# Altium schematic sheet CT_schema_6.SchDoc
size 252 x 245 mm
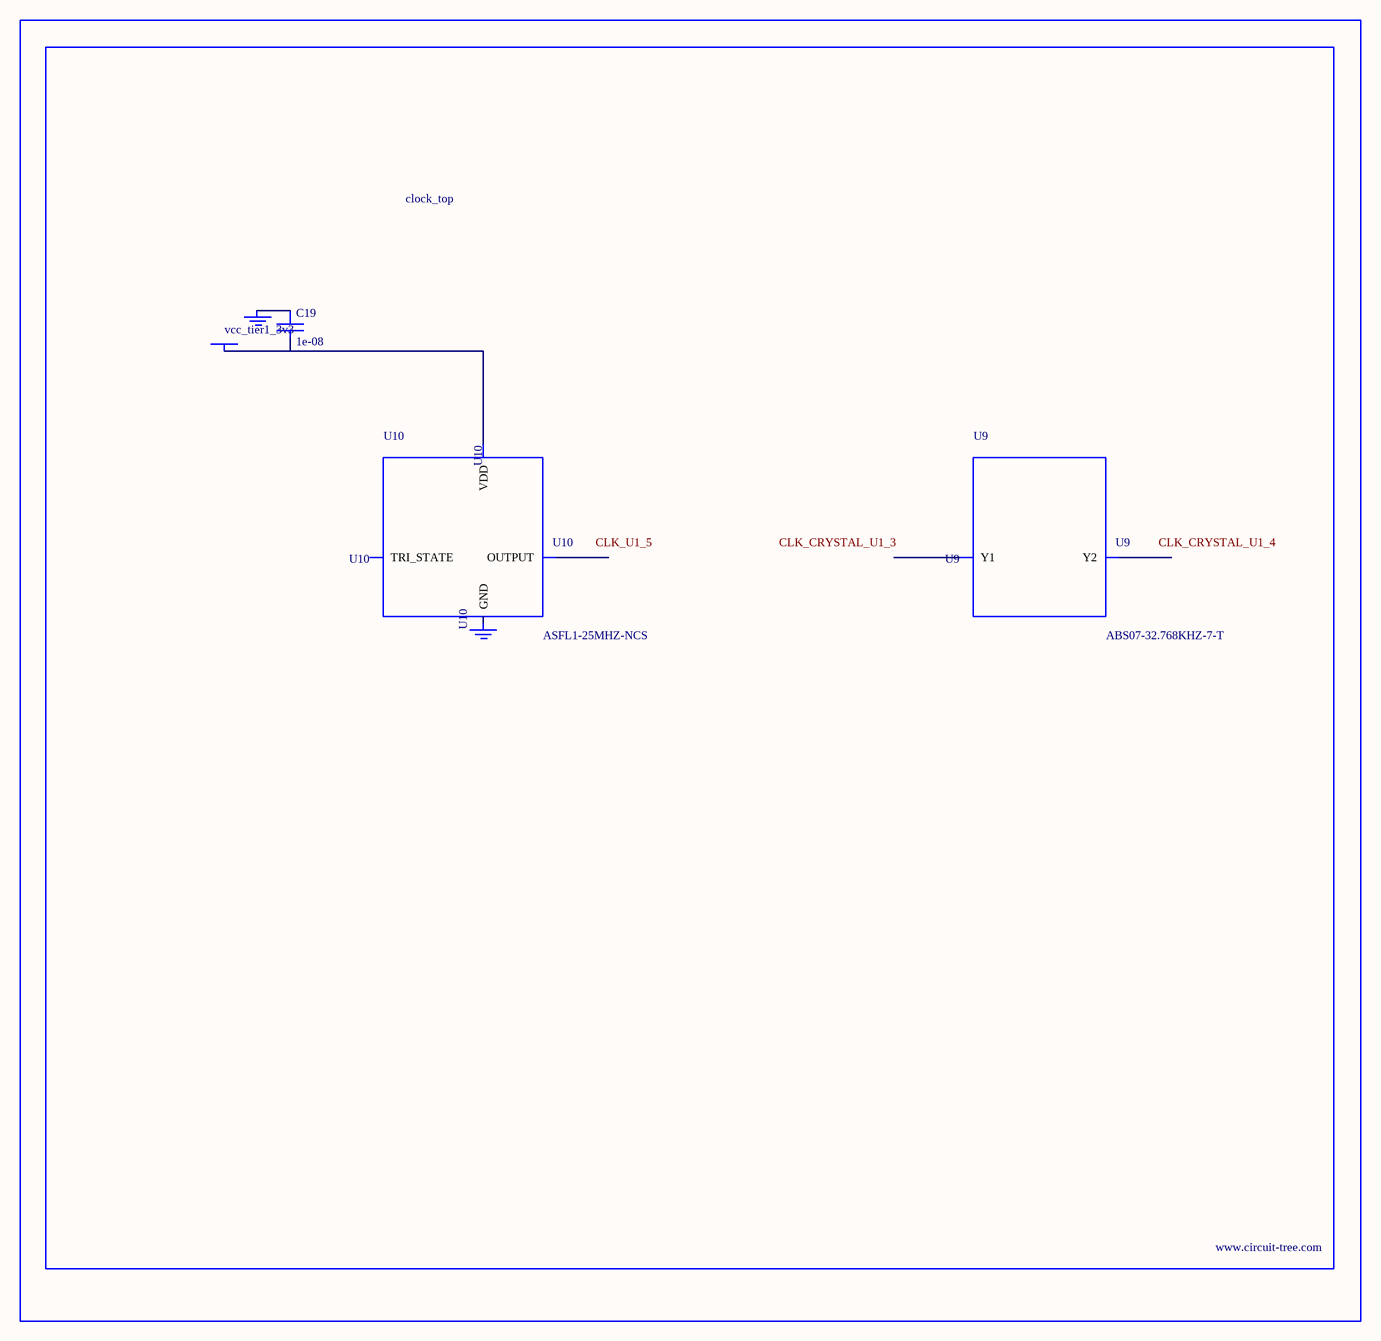
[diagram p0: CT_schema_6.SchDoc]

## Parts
BORDER5  (no value)
C19  1e-08  [C0402]
GND_INSTANCE_5_0  (no value)
GND_INSTANCE_5_1  (no value)
POWER_INSTANCE_5_0  vcc_tier1_3v3
U9  ABS07-32.768KHZ-7-T  [ABS07-32.768KHZ-7-T]
U10  ASFL1-25MHZ-NCS  [ASFL1]

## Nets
NetC19_1: C19.1 GND_INSTANCE_5_0.0(GND)
NetC19_2: C19.2 POWER_INSTANCE_5_0.0(PWR) U10.4(VDD)

Not connected (* = marked no-connect by the designer): GND_INSTANCE_5_1 0(GND); U9 1(Y1) 2(Y2); U10 1(TRI_STATE) 2(GND) 3(OUTPUT)

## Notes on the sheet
- Labels drawn without touching a wire or pin: CLK_CRYSTAL_U1_3, CLK_CRYSTAL_U1_4, CLK_U1_5

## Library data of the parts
BORDER5 = BORDER_PAGE5
C19 = C0402C103K3RAC
GND_INSTANCE_5_0 GND_INSTANCE_5_1 = GND
POWER_INSTANCE_5_0 = PWR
